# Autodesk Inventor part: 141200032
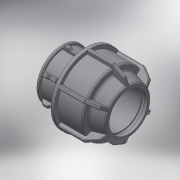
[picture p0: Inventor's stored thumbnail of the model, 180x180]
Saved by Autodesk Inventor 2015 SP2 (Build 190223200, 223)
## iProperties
Created: 2017-08
Part Number: 141200032
Material: Generic
Description: PLASSON L.14 END PLUG (SILVER) 32
Document SubType Name: Modeling
Designer: KIM
Density: 1 g/cm^3
Appearance: Default
Author: KIM
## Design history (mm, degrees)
derived "141200.ipt"
feature "Solid1::141200.ipt"
tag "TaggingFeature1"
body "Solid1"
other parameters: "d1" = 32, "d4" = 15 deg, "d5" = 35.64, "d6" = 11.7612, "d10" = 61, "d16" = 32.64, "d17" = 2.7, "d18" = 67, "d22" = 38.4, "d24" = 2.7, "d25" = 54.9, "d26" = 45.75, "d27" = 2.7, "d28" = 135 deg, "d29" = 1.62, "d31" = 1.6, "d44" = 0.64, "d46" = 150 deg, "d49" = 3.05, "d50" = 0, "d51" = 1.83, "d52" = 1.22, "d53" = 45 deg, "d54" = 13.4, "d55" = 5.36, "d56" = 3.05, "d57" = 0, "d58" = 0.96, "d59" = 0.64, "d61" = 360 deg, "d66" = 41.6, "d68" = 54, "d69" = 2.01, "d_" = 32, "E_" = 61, "H_" = 67, "l_" = 54
